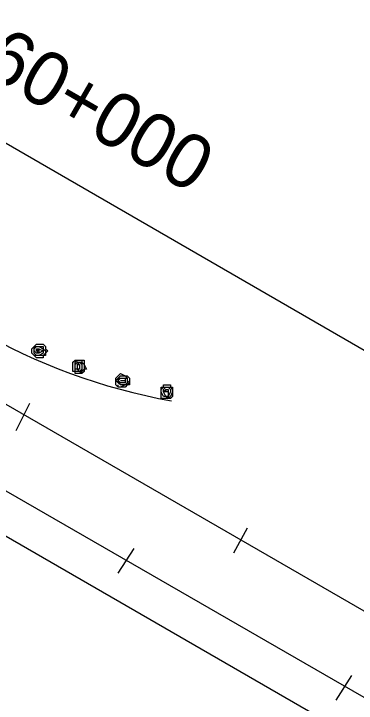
# Model space of a CAD drawing. Extents: x 36 to 2622, y -5330 to 219.
# Drawn here: x 2322.73 to 2341.59, y -4514.99 to -4477 of the extents above; entities that cross this region are included whole.
import ezdxf

# ---------------------------------------------------------------- set-up
doc = ezdxf.new("R2010")
doc.units = 0
doc.layers.add('2', color=7, linetype='Continuous')

msp = doc.modelspace()

# ---------------------------------------------------------------- linework, layer by layer
at = {"layer": '2'}
for p, q in [((2381.856, -4540.205), (2110.356, -4383.33)), ((2382.981, -4538.33), (2117.106, -4384.83)), ((2344.231, -4496.83), (2296.231, -4469.08)), ((2384.981, -4534.705), (2297.481, -4484.205)), ((2322.856, -4499.955), (2323.606, -4498.455)), ((2334.856, -4506.705), (2335.606, -4505.33)), ((2328.481, -4507.83), (2329.356, -4506.455)), ((2340.481, -4514.83), (2341.356, -4513.455))]:
    msp.add_line(p, q, dxfattribs=at)
for points in [[(2324.106, -4495.58), (2323.981, -4495.58), (2323.981, -4495.58), (2324.106, -4495.455), (2324.106, -4495.58), (2324.106, -4495.58), (2324.106, -4495.705), (2323.981, -4495.58), (2323.981, -4495.58), (2323.981, -4495.455), (2324.106, -4495.455), (2324.106, -4495.455), (2324.356, -4495.58), (2324.356, -4495.58), (2324.106, -4495.705), (2323.981, -4495.705), (2323.856, -4495.58), (2323.856, -4495.455), (2323.981, -4495.33), (2324.106, -4495.33), (2324.356, -4495.455), (2324.356, -4495.58), (2324.356, -4495.705), (2324.356, -4495.705), (2324.106, -4495.83), (2323.981, -4495.83), (2323.856, -4495.705), (2323.856, -4495.58), (2323.856, -4495.455), (2323.856, -4495.33), (2323.981, -4495.33), (2324.356, -4495.33), (2324.356, -4495.455), (2324.481, -4495.58), (2324.481, -4495.705), (2324.356, -4495.83), (2324.106, -4495.83), (2323.981, -4495.83), (2323.856, -4495.83), (2323.856, -4495.83), (2323.731, -4495.705), (2323.731, -4495.58), (2323.731, -4495.455), (2323.731, -4495.455), (2323.856, -4495.33), (2323.981, -4495.205), (2323.981, -4495.205), (2324.106, -4495.205), (2324.356, -4495.205), (2324.481, -4495.33), (2324.481, -4495.455), (2324.481, -4495.455), (2324.606, -4495.58), (2324.481, -4495.705), (2324.481, -4495.83), (2324.356, -4495.83), (2324.356, -4495.955), (2324.106, -4495.955), (2323.981, -4495.955), (2323.981, -4495.955), (2323.856, -4495.83)], [(2326.356, -4496.33), (2326.231, -4496.33), (2326.231, -4496.33), (2326.356, -4496.33), (2326.356, -4496.33), (2326.356, -4496.58), (2326.356, -4496.58), (2326.231, -4496.58), (2326.231, -4496.33), (2326.231, -4496.33), (2326.356, -4496.205), (2326.356, -4496.205), (2326.481, -4496.33), (2326.481, -4496.58), (2326.356, -4496.705), (2326.231, -4496.58), (2326.106, -4496.58), (2326.106, -4496.33), (2326.231, -4496.205), (2326.356, -4496.205), (2326.481, -4496.205), (2326.481, -4496.33), (2326.481, -4496.58), (2326.481, -4496.705), (2326.356, -4496.705), (2326.231, -4496.705), (2326.106, -4496.705), (2326.106, -4496.58), (2326.106, -4496.33), (2326.106, -4496.205), (2326.231, -4496.08), (2326.481, -4496.08), (2326.481, -4496.205), (2326.606, -4496.33), (2326.606, -4496.58), (2326.481, -4496.705), (2326.356, -4496.83), (2326.231, -4496.83), (2326.106, -4496.83), (2326.106, -4496.705), (2325.981, -4496.705), (2325.981, -4496.58), (2325.981, -4496.33), (2325.981, -4496.205), (2326.106, -4496.08), (2326.231, -4496.08), (2326.231, -4496.08), (2326.356, -4496.08), (2326.481, -4496.08), (2326.606, -4496.08), (2326.606, -4496.205), (2326.606, -4496.33), (2326.731, -4496.58), (2326.606, -4496.58), (2326.606, -4496.705), (2326.481, -4496.83), (2326.481, -4496.83), (2326.356, -4496.83), (2326.231, -4496.83), (2326.231, -4496.83), (2326.106, -4496.83)], [(2328.606, -4497.205), (2328.606, -4497.205), (2328.606, -4497.205), (2328.856, -4497.205), (2328.856, -4497.205), (2328.856, -4497.33), (2328.606, -4497.33), (2328.606, -4497.33), (2328.481, -4497.205), (2328.606, -4497.08), (2328.606, -4497.08), (2328.856, -4497.08), (2328.856, -4497.205), (2328.856, -4497.33), (2328.856, -4497.33), (2328.606, -4497.33), (2328.481, -4497.33), (2328.481, -4497.08), (2328.606, -4497.08), (2328.856, -4497.08), (2328.981, -4497.08), (2328.981, -4497.205), (2328.981, -4497.33), (2328.856, -4497.455), (2328.606, -4497.455), (2328.606, -4497.455), (2328.481, -4497.33), (2328.356, -4497.205), (2328.356, -4497.205), (2328.481, -4497.08), (2328.606, -4496.955), (2328.856, -4496.955), (2328.981, -4497.08), (2328.981, -4497.205), (2329.106, -4497.33), (2328.981, -4497.455), (2328.856, -4497.455), (2328.606, -4497.58), (2328.481, -4497.58), (2328.356, -4497.455), (2328.356, -4497.33), (2328.356, -4497.205), (2328.356, -4497.205), (2328.356, -4497.08), (2328.481, -4496.955), (2328.481, -4496.955), (2328.606, -4496.83), (2328.856, -4496.955), (2328.981, -4496.955), (2328.981, -4496.955), (2329.106, -4497.08), (2329.106, -4497.205), (2329.106, -4497.205), (2329.106, -4497.33), (2329.106, -4497.455), (2328.981, -4497.455), (2328.856, -4497.58), (2328.856, -4497.58), (2328.606, -4497.58), (2328.481, -4497.58), (2328.481, -4497.455)], [(2331.231, -4497.83), (2331.106, -4497.83), (2331.106, -4497.705), (2331.231, -4497.705), (2331.231, -4497.705), (2331.231, -4497.83), (2331.106, -4497.83), (2331.106, -4497.83), (2330.981, -4497.83), (2331.106, -4497.705), (2331.106, -4497.705), (2331.231, -4497.705), (2331.231, -4497.705), (2331.231, -4497.83), (2331.231, -4498.08), (2331.106, -4498.08), (2330.981, -4497.83), (2330.981, -4497.705), (2331.106, -4497.58), (2331.231, -4497.58), (2331.356, -4497.705), (2331.356, -4497.83), (2331.356, -4497.83), (2331.231, -4498.08), (2331.231, -4498.205), (2331.106, -4498.08), (2330.981, -4498.08), (2330.856, -4497.83), (2330.856, -4497.705), (2330.981, -4497.58), (2331.106, -4497.58), (2331.231, -4497.58), (2331.356, -4497.58), (2331.481, -4497.705), (2331.481, -4497.83), (2331.356, -4498.08), (2331.231, -4498.205), (2331.106, -4498.205), (2330.981, -4498.205), (2330.856, -4498.205), (2330.856, -4498.08), (2330.856, -4497.83), (2330.856, -4497.705), (2330.856, -4497.58), (2330.981, -4497.58), (2330.981, -4497.455), (2331.106, -4497.455), (2331.231, -4497.455), (2331.356, -4497.455), (2331.356, -4497.58), (2331.481, -4497.58), (2331.481, -4497.705), (2331.481, -4497.83), (2331.481, -4498.08), (2331.481, -4498.08), (2331.356, -4498.205), (2331.356, -4498.205), (2331.231, -4498.205), (2331.106, -4498.205), (2330.981, -4498.205), (2330.981, -4498.205)]]:
    msp.add_lwpolyline(points, dxfattribs=at)
msp.add_arc((2337.275, -4465.692), 33.156, 220.0491, 259.8292, dxfattribs=at)

# ---------------------------------------------------------------- texts
msp.add_text('60+000', height=3, rotation=329.9961, dxfattribs=at).set_placement((2320.856, -4480.204))

doc.saveas('drawing.dxf')
